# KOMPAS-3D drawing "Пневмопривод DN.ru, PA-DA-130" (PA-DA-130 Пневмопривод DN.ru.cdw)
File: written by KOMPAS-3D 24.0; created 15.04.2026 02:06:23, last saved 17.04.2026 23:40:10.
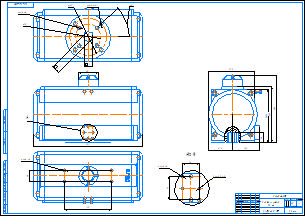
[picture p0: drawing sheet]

Document properties: Автор: DN.ru; Форматы листов документа: A1; Полное имя файла: PA-DA-130 Пневмопривод DN.ru.m3d; Масса: 8.9; Наименование: Пневмопривод DN.ru; Количество листов документа: 1; Примечание: D290-00297

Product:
- Part/product: Пневмопривод DN.ru  | designation PA-DA-130
    Масса: 8.9
    Раздел спецификации: Прочие изделия
    Примечание: D290-00297

Views: Вид 1, Вид:1, Проекционный вид 2, Выносной элемент 6, Выносной элемент А, Выносной элемент
Referenced files in C:\Работа\PA-DA-х Пневмопривод DN.ru\052\: PA-DA-052 Пневмопривод DN.ru.m3d
Referenced files in C:\Работа\PA-DA-х Пневмопривод DN.ru\130\: PA-DA-130 Пневмопривод DN.ru.m3d
Referenced files in C:\Program Files\ASCON\KOMPAS-3D v24\Templates\: Чертеж_DN.ru.cdt
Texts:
  objid
  viewid
  PA-DA-130
  Чертеж_DN.ru.cdt
  Пневмопривод
  Пневмопривод DN.ru
  PA-DA-130 Пневмопривод DN.ru
Dimensions and other numbers on the sheet: 0; 3; 2; 4; 55; 608; 301; 9; 4 отв.; 10; 22; 102; 70; 8; 7; 1; 2 отв.; 24; 32; 5; 1:1; 8,9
